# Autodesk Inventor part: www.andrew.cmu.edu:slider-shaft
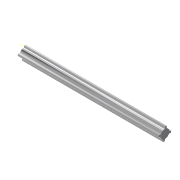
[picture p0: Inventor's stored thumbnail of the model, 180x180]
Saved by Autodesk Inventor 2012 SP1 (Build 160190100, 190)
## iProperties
Shininess: 64.0
Angle Display Precision: 2
Document Length Units: 11272
Document Angle Units: 11279
Document Time Units: 11290
Document Mass Units: 11283
Document Length Units Precision: 3
Document Angle Units Precision: 2
Created: 2008-04
Document SubType Name: Modeling
Density: 8.08 g/cm^3
Mass: 252.337 g
Surface Area: 128.621 cm^2
Volume: 31.2298 cm^3
Material: Stainless Steel
Density: 0.0
Volumn: 0.0
Area: 0.0
PropertySet Name: Model Information
Control State: 0
Master: False
Checked Out: False
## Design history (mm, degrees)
sketch "Sketch1"
  geometry: L1 (-69.329, 6.35)-(-69.329, 0); L2 (133.871, 6.35)-(-69.329, 6.35); L3 (133.871, 0)-(133.871, 6.35); L4 (-69.329, 0)-(133.871, 0); L5 (-69.329, 0)-(133.871, 0)
  constraints: 10 end point, 2 horizontal, 2 vertical, 1 other
  dimensions: "d1" = 203.2 distance of L2.start L1.start; "d3" = 6.35 distance of L3.start L2.start
revolve "RevolutionAngle1" sketch "Sketch1" stored, may be unused: angle "d4" = 360 deg
sketch "Sketch2"
  geometry: L1 (-2.174, 4.845)-(0.325, 5.3); L2 (-2.857, 8.593)-(-2.174, 4.845); L3 (-0.358, 9.049)-(-2.857, 8.593); L4 (0.325, 5.3)-(-0.358, 9.049); C1 r 6.35 at (0, 0) reference
  constraints: 8 end point
extrude "ExtrusionToPlane1" join sketch "Sketch2" stored distance "d7" = 3.302; taper "d8" = 0 deg
workplane "Work Plane1"
  workaxis "Work Axis1"
  workaxis "Work Axis3"
sketch "Sketch3"
  geometry: L1 (-2.54, 0)-(-2.54, 2.744); L2 (0, 2.744)-(0, 0); L3 (-2.54, 2.744)-(0, 2.744); L4 (0, -12.443)-(0, -15.188); L5 (0, -15.188)-(-2.54, -15.188); L6 (-2.54, -15.188)-(-2.54, -12.443); L7 (-2.54, -12.443)-(0, -12.443); A1 r 6.35 centre (-1.27, -6.222) between (-2.54, 0) and (0, 0) reference
  constraints: 14 end point, 2 perpendicular, 1 parallel, 15 other
  dimensions: "d11" = 360 deg dimension on A1.centre L1.start (derived)
extrude "Extrusion2" join sketch "Sketch3" stored distance "d13" = 25.4; taper "d14" = 0 deg
pattern_circular "Circular Pattern1" dims angle "d16" = 360 deg
body "Solid1"
other parameters: "d0" = 138.6586 (derived), "d2" = 6.35 (derived), "d5" = 0, "d6" = 0
